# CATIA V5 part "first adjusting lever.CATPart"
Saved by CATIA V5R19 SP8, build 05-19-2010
Part number: first adjusting lever
Bounding box of the stored display mesh (mm): x 43.917 to 168.843, y 76 to 114.6, z -22.089 to 186.399
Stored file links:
  G:\EU_thinkMotion\CFAO_2010\MMS_groupe1\MMS_groupe1\A reprendre\gduval\CFAO kinematic ok\first adjusting lever.CATPart
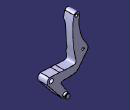
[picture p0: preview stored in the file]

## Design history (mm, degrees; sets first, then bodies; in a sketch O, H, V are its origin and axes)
Body1 (main body)
  Plane1: stored without definition
  Point1 to Point3: stored without definition
  Plane2: stored without definition
  Line1: stored without definition
  Sketch1 on Plane1, origin (0, 76, 0), H (-1, 0, 0), V (0, 0, 1)
    arc A1 centre (-78.802, 178.053) radius 8.4211 from (-70.4777, 179.3262) to (-86.4965, 181.4751) ccw
    point P1 (-78.802, 178.053)
    point P2 (-70.4777, 179.3262)
    point P3 (-86.4965, 181.4751)
    reference projected point E1 (-78.802, 178.053) from Point1
    spline S1 through (-86.4965, 181.4751) (-89.7885, 167.1844) (-90.8496, 153.92) (-90.8496, 132.6968) (-89.965, 117.3101) (-88.0196, 96.4407) (-83.7751, 75.2175) (-81.2991, 62.8374) (-80.831, 58.3271) (-82.4422, 53.3987) (-85.2854, 51.5032) (-92.2039, 50.8397) (-96.753, 50.8397) (-106.6982, 51.4182) (-116.1485, 52.1566)
    line L1 (-116.1485, 52.1566) -> (-130.4221, 53.2717)
    point P4 (-116.1485, 52.1566)
    point P5 (-130.4221, 53.2717)
    line L2 (-130.4221, 53.2717) -> (-161.5788, 54.7051)
    point P6 (-130.4221, 53.2717)
    arc A2 centre (-156.193, 43.188) radius 12.7142 from (-161.5788, 54.7051) to (-166.7715, 36.135) ccw
    point P8 (-156.193, 43.188)
    reference projected point E2 (-156.193, 43.188) from Point2
    line L3 (-166.7715, 36.135) -> (-123.6853, -17.1019)
    point P10 (-123.6853, -17.1019)
    arc A3 centre (-115.24, -12.521) radius 9.6077 from (-123.6853, -17.1019) to (-108.888, -5.3127) ccw
    point P11 (-115.24, -12.521)
    point P12 (-123.6853, -17.1019)
    reference projected point E3 (-115.24, -12.521) from Point3
    line L4 (-108.888, -5.3127) -> (-124.256, 17.9335)
    point P14 (-124.256, 17.9335)
    spline S2 through (-124.256, 17.9335) (-125.8485, 20.3425) (-124.256, 25.0101) (-118.6872, 26.8003) (-110.8437, 26.8003) (-101.1114, 26.8003) (-93.9509, 26.8003) (-88.7313, 27.8204) (-81.8792, 29.2321) (-75.6732, 33.1953) (-69.1214, 40.5334) (-60.2579, 51.4749) (-52.6648, 62.1263) (-43.9169, 76.8276) (-47.3696, 86.3969) (-54.1835, 97.4041) (-59.5642, 106.159) (-68.7902, 134.9487) (-72.2735, 154.6235) (-70.4398, 177.058) (-70.4777, 179.3262)
    point P15 (-86.4965, 181.4751)
    point P16 (-116.1485, 52.1566)
    point P17 (-106.6982, 51.4182)
    point P18 (-124.256, 17.9335)
    point P19 (-125.8485, 20.3425)
    point P20 (-70.4398, 177.058)
    point P21 (-70.4777, 179.3262)
    radius A1 = 8.4211
    coincidence: P1 E1, P15 P3, P16 P4, L1 P17, P8 E2, P6 P5, P11 E3, P12 P10, P18 P14, P19 L4, P20 A1, P21 A1, P2 P21
    tangency: L4 A2
  Pad1: profile Sketch1, direction (0, 1, 0), up to Plane2
  Line2: stored without definition
  Sketch2 on start face of Pad1, origin (156.193, 76, 43.188), H (1, 0, 0), V (0, 0, 1)
    point P1 (0, 0)
    intersected point E1 (0, 0) from Line1
    coincidence: E1 P1
  Hole1: placed by Sketch2, at (156.193, 76, 43.188) direction (0, 1, 0), diameter 13, through (limit type 6)
  Line3: stored without definition
  Line4: stored without definition
  Sketch3 on end face of Pad1, origin (78.802, 104.1, 178.053), H (1, 0, 0), V (0, 0, -1)
    point P1 (0, 0)
    intersected point E1 (0, 0) from Line3
    coincidence: E1 P1
  Hole2: placed by Sketch3, at (78.802, 104.1, 178.053) direction (0, -1, 0), diameter 10, through (limit type 6)
  Sketch4 on end face of Pad1, origin (59.016, 104.1, 79.603), H (1, 0, 0), V (0, 0, -1)
    point P1 (0, 0)
    intersected point E1 (0, 0) from Line4
    coincidence: E1 P1
  Hole3: placed by Sketch4, at (59.016, 104.1, 79.603) direction (0, -1, 0), diameter 8, depth 18
  Sketch5 on end face of Pad1, origin (0, 104.1, 0), H (-1, 0, 0), V (0, 0, 1)
    circle A1 centre (-115.24, -12.521) radius 6.5
    point P1 (-115.24, -12.521)
    reference projected point E1 (-115.24, -12.521) from Line2
    radius A1 = 6.5
    coincidence: P1 E1
  Pad2: profile Sketch5, direction (0, 1, 0), length 10.5
  Plane3: type 2Lines, Element1 Line2, Element2 Line1
  Sketch6 on Plane3, origin (80.7868, 0, -59.3883), H (0, -1, 0), V (0.5923, 0, 0.8057)
    line L1 (-112.6, 64.6684) -> (-111.1, 64.6684)
    line L2 (-111.1, 64.6684) -> (-111.1, 63.1684)
    line L3 (-111.1, 63.1684) -> (-112.6, 63.1684)
    line L4 (-112.6, 63.1684) -> (-112.6, 64.6684)
    reference intersected line E1 (-114.6, 51.6684) -> (-114.6, 64.6684) from end face of Pad2
    reference projected line E2 through (0, 58.1684) direction (-1, 0) from axis of face of Pad2 from Sketch5.A1
    distance E1 L4 = 2
    distance L4 L2 = 1.5
    distance L1 E2 = 6.5
    distance L3 L1 = 1.5
    horizontal: L1 H, L3 H
    vertical: L2 V, L4 V
  Groove1: profile Sketch6, axis axis of face of Pad2 from Sketch5.A1, angle 360
  Plane4: type 2Lines, Element1 Line3, Element2 Line4
  Sketch7 on Plane4, origin (41.3477, 0, -8.3099), H (0, 1, 0), V (0.197, 0, 0.9804)
    spline S1 through (64.8492, 173.3936) (76.0986, 175.7668) (82.65, 158.0353) (83.2922, 127.3645) (76.3887, 91.6969) (62.3322, 100.8758)
    line L1 (64.8492, 173.3936) -> (62.3322, 100.8758)
    point P1 (64.8492, 173.3936)
    point P2 (62.3322, 100.8758)
    point P3 (64.8492, 173.3936)
    point P4 (62.3322, 100.8758)
    coincidence: P3 P1, P4 P2
  Pocket1: profile Sketch7, direction (0.9804, 0, -0.197), through (limit type 6), opposite side through (limit type 6)
  Fillet1: radius 5, on edge [face of Pocket1 from Sketch7.S1 | start face of Pad1]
